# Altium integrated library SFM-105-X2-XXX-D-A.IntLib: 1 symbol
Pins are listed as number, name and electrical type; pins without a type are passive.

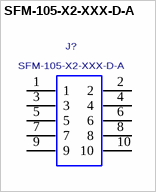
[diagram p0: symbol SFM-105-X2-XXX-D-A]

## SFM-105-X2-XXX-D-A
designator J?
SOCKET STRIP, .050" (1.27mm) PITCH, SURFACE MOUNT.; MANUFACTURER: SAMTEC
footprint SFM-105-X2-XXX-D-A
pins: 1, 2, 3, 4, 5, 6, 7, 8, 9, 10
